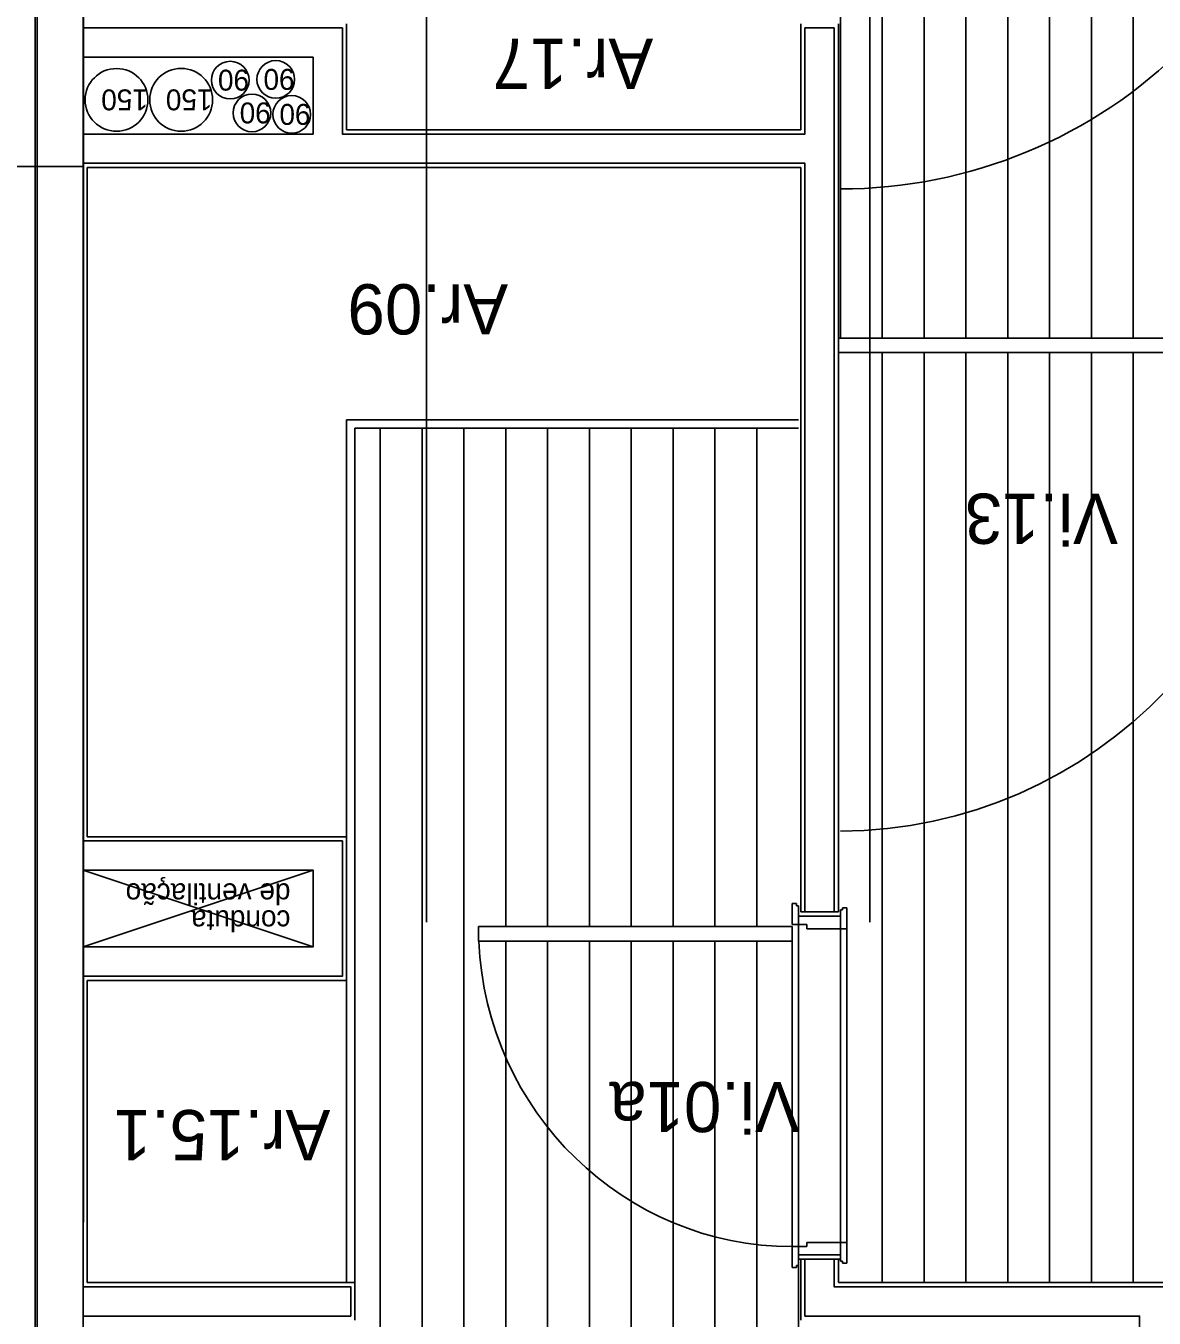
# Model space of a CAD drawing. Extents: x 1248 to 1356, y -443 to -224.
# Drawn here: x 1291.197 to 1293.894, y -235.875 to -232.785 of the extents above; entities that cross this region are included whole.
import ezdxf

# ---------------------------------------------------------------- set-up
doc = ezdxf.new("R2010")
doc.units = 0
for name, color, linetype in [('corte', 7, 'Continuous'), ('estereoctomias', 7, 'Continuous'), ('Level 1', 7, 'Continuous'), ('Level 10', 7, 'Continuous'), ('Level 13', 7, 'Continuous'), ('Level 4', 7, 'Continuous'), ('Level 40', 7, 'Continuous'), ('Level 41', 7, 'Continuous'), ('revestimentos', 7, 'Continuous'), ('vermelhos-cont', 7, 'Continuous'), ('vermelhos-tracej', 7, 'Continuous')]:
    doc.layers.add(name, color=color, linetype=linetype)

msp = doc.modelspace()

# ---------------------------------------------------------------- linework, layer by layer
at = {"layer": 'corte'}
for p, q in [((1291.9534, -232.7903), (1291.3335, -232.7903)), ((1291.9534, -232.7903), (1291.9534, -233.044)), ((1293.1288, -232.7903), (1293.0588, -232.7903)), ((1291.8834, -232.8603), (1291.3335, -232.8603)), ((1291.3335, -232.8603), (1291.3335, -233.044)), ((1291.8834, -232.8603), (1291.8834, -233.044)), ((1291.8834, -233.044), (1291.3335, -233.044)), ((1291.9534, -234.734), (1291.3335, -234.734)), ((1291.9534, -234.734), (1291.9534, -235.0576)), ((1291.8834, -234.804), (1291.3335, -234.804)), ((1291.8834, -234.804), (1291.8834, -234.9876)), ((1291.8834, -234.9876), (1291.3335, -234.9876)), ((1291.9534, -235.0576), (1291.3335, -235.0576))]:
    msp.add_line(p, q, dxfattribs=at)
msp.add_lwpolyline([(1291.1042, -233.1214), (1291.3342, -233.1214), (1291.3342, -232.3214), (1291.1042, -232.3214)], close=True, dxfattribs=at)
at = {"layer": 'estereoctomias'}
for points in [[(1293.1288, -234.904), (1293.0588, -234.904), (1293.0588, -233.114), (1291.3335, -233.114), (1291.3335, -233.044), (1291.8834, -233.044), (1291.8834, -232.8603), (1291.3335, -232.8603), (1291.3335, -232.7903), (1291.9534, -232.7903), (1291.9534, -233.044), (1293.0588, -233.044), (1293.0588, -232.7903), (1293.1288, -232.7903)], [(1291.3342, -233.1214), (1291.2235, -233.1214), (1291.2235, -238.1713), (1291.3335, -238.1713)], [(1291.3335, -235.0576), (1291.9534, -235.0576), (1291.9534, -234.734), (1291.3335, -234.734), (1291.3335, -234.804), (1291.8834, -234.804), (1291.8834, -234.9876), (1291.3335, -234.9876)], [(1294.3288, -235.734), (1294.3288, -235.8701), (1293.9287, -235.8701), (1293.9287, -239.084), (1293.8587, -239.084), (1293.8587, -235.8701), (1293.0588, -235.8701), (1293.0588, -235.734), (1293.1288, -235.734), (1293.1288, -235.8001), (1294.2588, -235.8001), (1294.2588, -235.734)], [(1291.9734, -235.8701), (1291.3335, -235.8701), (1291.3335, -235.8001), (1291.9734, -235.8001)]]:
    msp.add_lwpolyline(points, close=True, dxfattribs=at)
at = {"layer": 'Level 1'}
for p, q in [((1291.2235, -228.764), (1291.2235, -239.084)), ((1291.3335, -228.764), (1291.3335, -233.044)), ((1293.0588, -233.044), (1293.0588, -232.7903)), ((1293.1288, -234.904), (1293.1288, -232.7903)), ((1291.3335, -233.044), (1291.3335, -234.734)), ((1291.9534, -233.044), (1293.0588, -233.044)), ((1291.3335, -233.114), (1293.0588, -233.114)), ((1293.0588, -234.904), (1293.0588, -233.114)), ((1291.3335, -234.734), (1291.3335, -235.0576)), ((1293.0488, -234.904), (1293.1388, -234.904)), ((1291.3335, -235.0576), (1291.3335, -235.8701)), ((1293.0438, -235.734), (1293.1438, -235.734)), ((1293.0588, -235.8701), (1293.0588, -235.734)), ((1293.1288, -235.734), (1293.1288, -235.8001)), ((1291.9734, -235.8001), (1291.3335, -235.8001)), ((1291.9734, -235.8701), (1291.9734, -235.8001)), ((1293.1288, -235.8001), (1294.2588, -235.8001)), ((1291.3335, -235.8701), (1291.3335, -239.084)), ((1291.3335, -235.8701), (1291.9734, -235.8701)), ((1293.8587, -235.8701), (1293.0588, -235.8701)), ((1293.8587, -239.084), (1293.8587, -235.8701))]:
    msp.add_line(p, q, dxfattribs=at)
at = {"layer": 'Level 10'}
for p, q in [((1293.1438, -233.5317), (1293.1438, -228.774)), ((1293.2438, -233.5317), (1293.2438, -232.0103)), ((1293.3438, -233.5317), (1293.3438, -232.0103)), ((1293.4438, -233.5317), (1293.4438, -232.0103)), ((1293.5438, -233.5317), (1293.5438, -232.0103)), ((1293.6438, -233.5317), (1293.6438, -232.0103)), ((1293.7438, -233.5317), (1293.7438, -232.0103)), ((1293.8438, -233.5317), (1293.8438, -232.0103)), ((1293.2438, -233.5667), (1293.2438, -235.7901)), ((1293.3438, -233.5667), (1293.3438, -235.7901)), ((1293.4438, -233.5667), (1293.4438, -235.7901)), ((1293.5438, -233.5667), (1293.5438, -235.7901)), ((1293.6438, -233.5667), (1293.6438, -235.7901)), ((1293.7438, -233.5667), (1293.7438, -235.7901)), ((1293.8438, -233.5667), (1293.8438, -235.7901)), ((1292.0438, -239.074), (1292.0438, -233.7476)), ((1292.1438, -239.074), (1292.1438, -233.7476)), ((1292.2438, -239.074), (1292.2438, -233.7476)), ((1292.3438, -234.939), (1292.3438, -233.7476)), ((1292.4438, -234.939), (1292.4438, -233.7476)), ((1292.5438, -234.939), (1292.5438, -233.7476)), ((1292.6438, -234.939), (1292.6438, -233.7476)), ((1292.7438, -234.939), (1292.7438, -233.7476)), ((1292.8438, -234.939), (1292.8438, -233.7476)), ((1292.9438, -234.939), (1292.9438, -233.7476)), ((1293.0438, -235.704), (1293.0438, -234.934)), ((1293.1438, -235.694), (1293.1438, -234.944)), ((1292.3438, -239.074), (1292.3438, -234.974)), ((1292.4438, -239.074), (1292.4438, -234.974)), ((1292.5438, -239.074), (1292.5438, -234.974)), ((1292.6438, -239.074), (1292.6438, -234.974)), ((1292.7438, -239.074), (1292.7438, -234.974)), ((1292.8438, -239.074), (1292.8438, -234.974)), ((1292.9438, -239.074), (1292.9438, -234.974)), ((1293.0438, -235.734), (1293.0438, -239.074))]:
    msp.add_line(p, q, dxfattribs=at)
at = {"layer": 'Level 13'}
for p, q in [((1293.1388, -233.5317), (1294.2438, -233.5317)), ((1293.1388, -233.5667), (1294.2438, -233.5667)), ((1291.9634, -233.7276), (1293.0438, -233.7276)), ((1291.9634, -233.7276), (1291.9634, -235.7901)), ((1291.9834, -233.7476), (1293.0438, -233.7476)), ((1291.9834, -233.7476), (1291.9834, -235.7901)), ((1293.0288, -234.884), (1293.0288, -234.934)), ((1293.0388, -234.884), (1293.0288, -234.884)), ((1293.0388, -234.889), (1293.0388, -234.884)), ((1293.0438, -234.889), (1293.0388, -234.889)), ((1293.0438, -234.934), (1293.0438, -234.889)), ((1293.0438, -234.914), (1293.1438, -234.914)), ((1293.0438, -234.934), (1293.0438, -234.914)), ((1293.1438, -234.944), (1293.1438, -234.899)), ((1293.1438, -234.899), (1293.1488, -234.899)), ((1293.1438, -234.914), (1293.1438, -234.944)), ((1293.1488, -234.899), (1293.1488, -234.894)), ((1293.1488, -234.894), (1293.1588, -234.894)), ((1293.1588, -234.894), (1293.1588, -234.944)), ((1292.2788, -234.939), (1293.0288, -234.939)), ((1292.2788, -234.974), (1292.2788, -234.939)), ((1293.0288, -234.934), (1293.0438, -234.934)), ((1293.0288, -234.939), (1293.0288, -234.974)), ((1293.0638, -234.934), (1293.0438, -234.934)), ((1293.0638, -234.944), (1293.0638, -234.934)), ((1293.1438, -234.944), (1293.0638, -234.944)), ((1293.1588, -234.944), (1293.1438, -234.944)), ((1293.0288, -234.974), (1292.2788, -234.974)), ((1293.0288, -235.754), (1293.0288, -235.704)), ((1293.0288, -235.704), (1293.0438, -235.704)), ((1293.0638, -235.704), (1293.0438, -235.704)), ((1293.0438, -235.704), (1293.0438, -235.724)), ((1293.0438, -235.704), (1293.0438, -235.749)), ((1293.1438, -235.694), (1293.0638, -235.694)), ((1293.0638, -235.694), (1293.0638, -235.704)), ((1293.1438, -235.724), (1293.1438, -235.694)), ((1293.1588, -235.694), (1293.1438, -235.694)), ((1293.1438, -235.694), (1293.1438, -235.739)), ((1293.1588, -235.744), (1293.1588, -235.694)), ((1293.0388, -235.754), (1293.0288, -235.754)), ((1293.0438, -235.749), (1293.0388, -235.749)), ((1293.0388, -235.749), (1293.0388, -235.754)), ((1293.0438, -235.724), (1293.1438, -235.724)), ((1293.1438, -235.739), (1293.1488, -235.739)), ((1293.1488, -235.739), (1293.1488, -235.744)), ((1293.1488, -235.744), (1293.1588, -235.744))]:
    msp.add_line(p, q, dxfattribs=at)
at = {"layer": 'Level 4'}
for p, q in [((1293.1588, -234.944), (1293.1588, -235.694)), ((1293.0288, -235.704), (1293.0288, -234.974))]:
    msp.add_line(p, q, dxfattribs=at)
msp.add_arc((1293.1438, -232.0103), 1.165, 270, 0.001, dxfattribs=at)
for centre, major_axis, ratio, start_param, end_param in [((1293.1438, -233.5667), (0, -1.1437), 0.96182, 0, 1.570796), ((1293.0288, -234.9408), (0, 0.7632), 0.982661, 1.614288, 3.141593)]:
    msp.add_ellipse(centre, major_axis=major_axis, ratio=ratio, start_param=start_param, end_param=end_param, dxfattribs=at)
at = {"layer": 'Level 41'}
for p, q in [((1291.8834, -234.9876), (1291.3335, -234.804)), ((1291.8834, -234.804), (1291.3335, -234.9876))]:
    msp.add_line(p, q, dxfattribs=at)
for centre, radius in [((1291.6853, -232.9151), 0.045), ((1291.7941, -232.9133), 0.045), ((1291.4135, -232.9623), 0.075), ((1291.5679, -232.9622), 0.075), ((1291.7372, -232.9935), 0.045), ((1291.8322, -232.997), 0.045)]:
    msp.add_circle(centre, radius, dxfattribs=at)
at = {"layer": 'revestimentos'}
for p, q in [((1291.9634, -232.7803), (1291.9634, -233.034)), ((1293.0488, -233.034), (1293.0488, -232.7803)), ((1293.1388, -234.904), (1293.1388, -232.7803)), ((1291.9634, -233.034), (1293.0488, -233.034)), ((1291.3435, -233.124), (1293.0488, -233.124)), ((1291.3435, -233.124), (1291.3435, -234.724)), ((1293.0488, -234.904), (1293.0488, -233.124)), ((1291.9634, -234.724), (1291.3435, -234.724)), ((1291.9634, -235.0676), (1291.3435, -235.0676)), ((1291.3435, -235.0676), (1291.3435, -235.7901)), ((1293.0488, -235.8801), (1293.0488, -235.734)), ((1293.1388, -235.734), (1293.1388, -235.7901)), ((1291.9834, -235.7901), (1291.3435, -235.7901)), ((1291.9834, -235.8801), (1291.9834, -235.7901)), ((1293.1388, -235.7901), (1294.2488, -235.7901))]:
    msp.add_line(p, q, dxfattribs=at)
at = {"layer": 'vermelhos-cont'}
msp.add_line((1291.2192, -225.5674), (1291.2192, -250.7923), dxfattribs=at)
at = {"layer": 'vermelhos-tracej'}
for p, q in [((1292.154, -234.928), (1292.154, -224.3117)), ((1293.2139, -234.928), (1293.2139, -224.3117))]:
    msp.add_line(p, q, dxfattribs=at)

# ---------------------------------------------------------------- texts
at = {"layer": 'Level 40'}
for s, p in [('Ar.17', (1292.6963, -232.816)), ('Ar.09', (1292.3494, -233.403)), ('Vi.13', (1293.807, -233.9038)), ('Vi.01a', (1293.0463, -235.3103)), ('Ar.15.1', (1291.9245, -235.3775))]:
    msp.add_text(s, height=0.12, rotation=180, dxfattribs=at).set_placement(p)
at = {"layer": 'Level 41'}
for s, p in [('90', (1291.7303, -232.8901)), ('90', (1291.8391, -232.8883)), ('150', (1291.4885, -232.9373)), ('150', (1291.6429, -232.9372)), ('90', (1291.7822, -232.9685)), ('90', (1291.8772, -232.972)), ('de ventilação ', (1291.8293, -234.8355)), ('conduta', (1291.8293, -234.9))]:
    msp.add_text(s, height=0.05, rotation=180, dxfattribs=at).set_placement(p)

doc.saveas('drawing.dxf')
